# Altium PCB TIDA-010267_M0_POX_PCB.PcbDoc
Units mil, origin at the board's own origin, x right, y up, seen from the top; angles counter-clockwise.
Board outline 2000 x 1062.99 mil, 2 copper layers (Top Layer, Bottom Layer), stack 61.2 mil thick; 42 components, 32 nets, 124 pads, 44 vias.
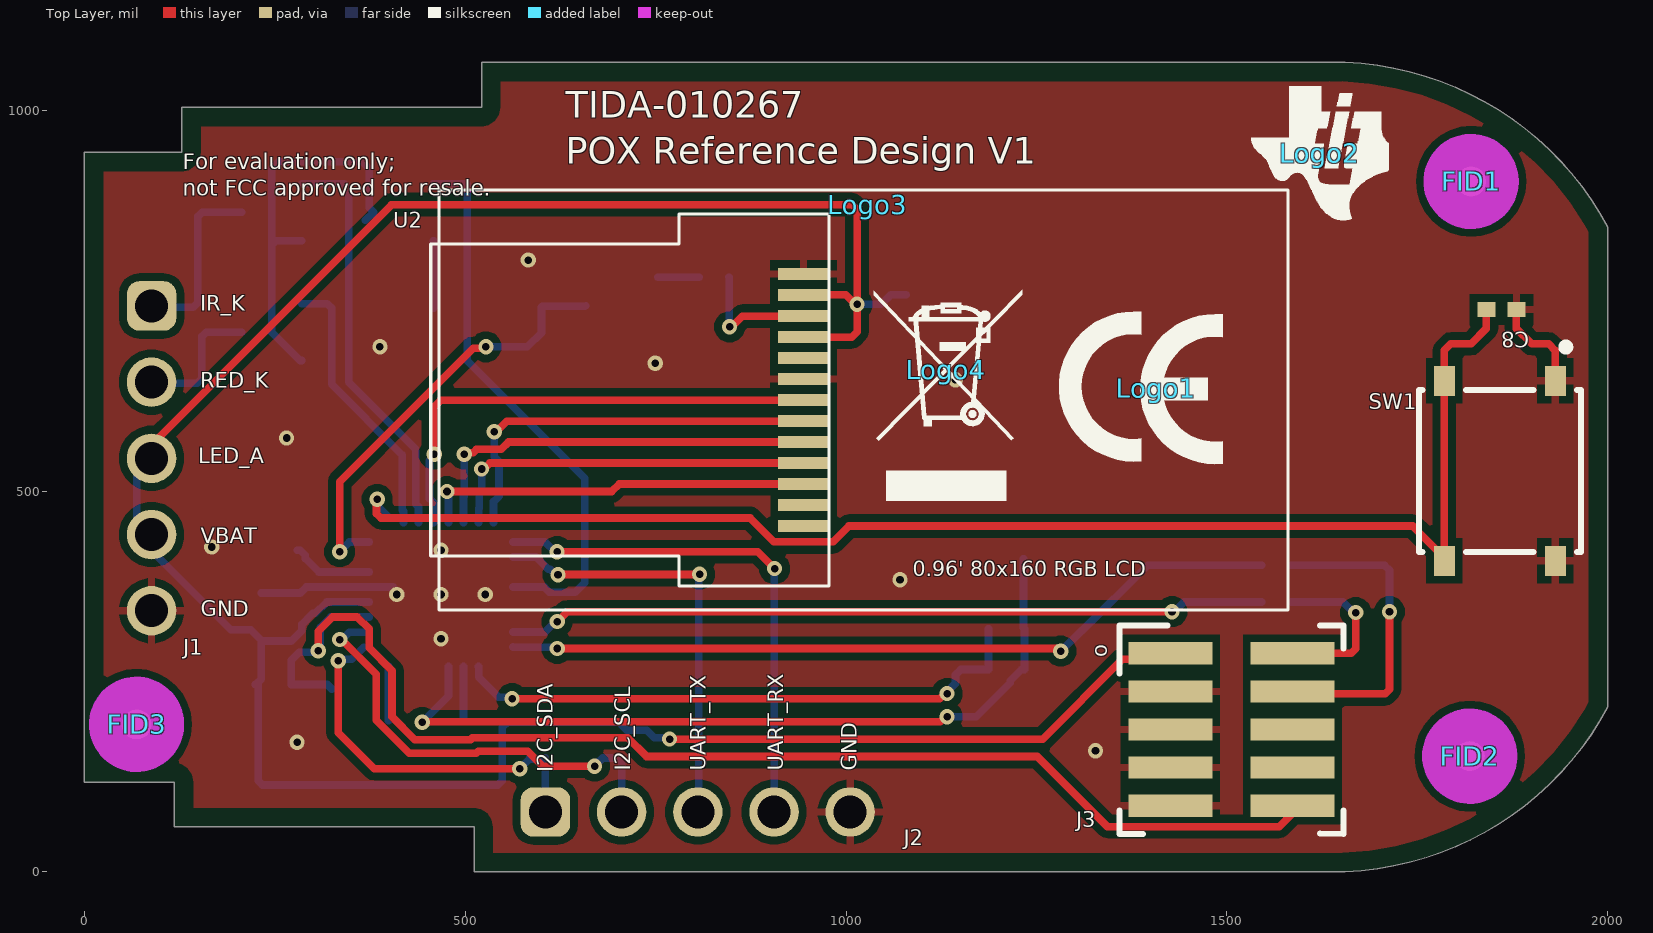
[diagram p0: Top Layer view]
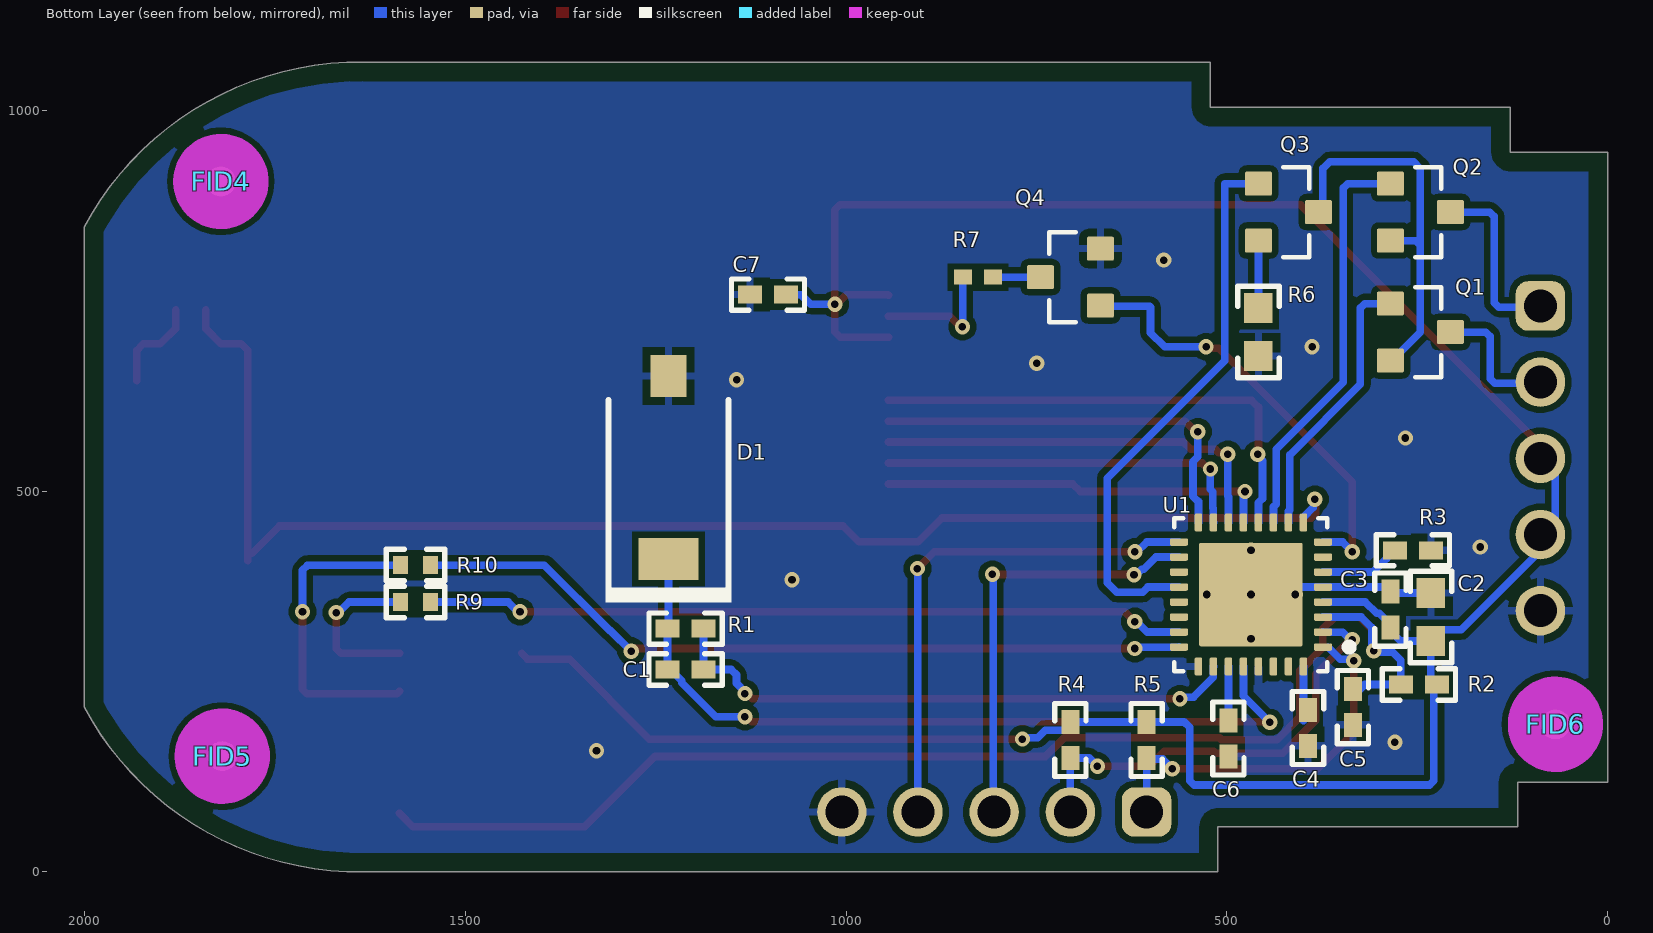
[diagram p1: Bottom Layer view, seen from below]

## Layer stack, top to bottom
Top Solder: solder mask 0.4, Solder Resist, Dk 3.5
Top Layer: signal copper 1.4
Dielectric1: dielectric 58.4, FR-4 High Tg, Dk 4.8
Bottom Layer: signal copper 1.4
Bottom Solder: solder mask 0.4, Solder Resist, Dk 3.5

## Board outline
0,118.11 0,944.88 127.95,944.88 127.95,1003.94 521.65,1003.94 521.65,1062.99 1633.86,1062.99 cw(c1638.25,652.6) 2000,846.46 2000,216.54 cw(c1638.25,410.39) 1633.86,0 511.81,0 511.81,59.06 118.11,59.06 118.11,118.11

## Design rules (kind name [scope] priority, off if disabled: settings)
AcuteAngle [All] p1: minimum=4.50000000000000E+0001 checktracksonly=FALSE
AssemblyTestPointUsage [All] p1: valid=2
BoardOutlineClearance BoardOutlineClearance_MountingHoles [OnCopper and InComponentClass('Mounting Holes')] p1: gap=39.37 ignorepadtopadclearanceinfootprint=FALSE
BoardOutlineClearance BoardOutlineClearance_Poly [OnCopper and IsPoly] p2: gap=25 ignorepadtopadclearanceinfootprint=FALSE
BoardOutlineClearance [OnCopper and Not InComponentClass('Logo') and not InComponentClass('FiducialMark') and not InRegion(1000,500,4000,800) and not StringText] p3: gap=10 ignorepadtopadclearanceinfootprint=FALSE
Clearance Clearance_1 [InNamedPolygon('GND_L01_P002')] p1: gap=10 ignorepadtopadclearanceinfootprint=FALSE except(0: Arc-Hole Track-Hole SMDPad-Hole THPad-Hole Via-Hole Fill-Hole Poly-Hole Region-Hole Text-Hole)
Clearance Clearance_Keepouts [((IsTrack Or IsArc) And Not InPoly) And IsFree and IsKeepOut vs ((IsTrack Or IsArc) And Not InPoly) And IsFree and IsKeepOut] p2: gap=0 ignorepadtopadclearanceinfootprint=FALSE
Clearance Clearance_Poly [InPolygon] p3: gap=8 ignorepadtopadclearanceinfootprint=TRUE
Clearance Clearance_FiducialMark [IsKeepOut and InComponentClass('FiducialMark') vs IsPad and InComponentClass('FiducialMark')] p4: gap=0 ignorepadtopadclearanceinfootprint=FALSE
Clearance [All] p5: gap=7.87 ignorepadtopadclearanceinfootprint=TRUE
ComponentClearance ComponentClearance_MountingHoles_FiducialMarks [InComponentClass('Mounting Holes') vs InComponentClass('FiducialMark')] p1: gap=50 collisioncheckmode=3 verticalgap=10 showdistances=FALSE
ComponentClearance ComponentClearance_Shunt [InComponentClass('Header') vs InComponentClass('Shunt')] p2: gap=0 collisioncheckmode=3 verticalgap=0 showdistances=FALSE
ComponentClearance ComponentClearance_Logo [InComponentClass('Logo')] p3: gap=0 collisioncheckmode=3 verticalgap=0 showdistances=FALSE
ComponentClearance ComponentClearance_ScrewToNut [(HasFootprint('NY PMS 440 0025 PH')) vs (HasFootprint('Keystone_1902C'))] p4: gap=5 collisioncheckmode=3 verticalgap=10 showdistances=FALSE
ComponentClearance ComponentClearance_MountingHoles [InComponentClass('Mounting Holes')] p5: gap=100 collisioncheckmode=3 verticalgap=100000 showdistances=FALSE
ComponentClearance ComponentClearance_SmallPassives [HasFootprint('0201*') or HasFootprint('0402*') or HasFootprint('0508') or HasFootprint('0603*') or HasFootprint('0612') or HasFootprint('0805*') or HasFootprint('0815*') or HasFootprint('0830*') or HasFootprint('1206*') or HasFootprint('1210*') or HasFootprint('1808*') or HasFootprint('1812*') or HasFootprint('1825*') or HasFootprint('2010*') or HasFootprint('2220*') or HasFootprint('2225*') or HasFootprint('2512*') or HasFootprint('2728*') or HasFootprint('3518*') vs HasFootprint('0201*') or HasFootprint('0402*') or HasFootprint('0508') or HasFootprint('0603*') or HasFootprint('0612') or HasFootprint('0805*') or HasFootprint('0815*') or HasFootprint('0830*') or HasFootprint('1206*') or HasFootprint('1210*') or HasFootprint('1808*') or HasFootprint('1812*') or HasFootprint('1825*') or HasFootprint('2010*') or HasFootprint('2220*') or HasFootprint('2225*') or HasFootprint('2512*') or HasFootprint('2728*') or HasFootprint('3518*')] p6: gap=14.96 collisioncheckmode=3 verticalgap=10 showdistances=FALSE
ComponentClearance ComponentClearance_THtoSMT [IsThruComponent vs IsSMTComponent] p7: gap=30 collisioncheckmode=3 verticalgap=30 showdistances=FALSE
ComponentClearance ComponentClearance_THtoTH [IsThruComponent vs IsThruComponent] p8: gap=20 collisioncheckmode=3 verticalgap=30 showdistances=FALSE
ComponentClearance [All] p9: gap=20 collisioncheckmode=3 verticalgap=10 showdistances=FALSE
DiffPairsRouting [All] p1: maxlimit=100 minlimit=10 mostfreqgap=10 toplayer_minwidth=15 toplayer_maxwidth=15 toplayer_prefwidth=15 bottomlayer_minwidth=15 bottomlayer_maxwidth=15 bottomlayer_prefwidth=15 maxuncoupledlength=1000
FabricationTestPointUsage TestPointUsage [All] p1: valid=2 allowmultiple=FALSE
FabricationTestpoint Testpoint [All] p1: side=3 testpointundercomponent=TRUE minsize=40 maxsize=100 preferedsize=60 minholesize=0 maxholesize=40 preferedholesize=32 testpointgrid=1 allowsidetop=TRUE allowsidebottom=TRUE usegrid=TRUE gridtolerance=0.01
FanoutControl Fanout_LCC [IsLCC] p1: bgadir=Out bgaviamode=Centered fanoutstyle=Auto fanoutdirection=Alternating viagrid=1 // Fanout_LCC (Default Rule)
FanoutControl Fanout_BGA [IsBGA] p2: bgadir=Out bgaviamode=Centered fanoutstyle=Auto fanoutdirection=Alternating viagrid=1 // Fanout_BGA (Default Rule)
HoleSize [All] p1: absolutevalues=TRUE maxlimit=251 minlimit=7.87 maxpercent=80.000 minpercent=20.000
MinimumAnnularRing MinimumAnnularRing_ThermalPadVias [IsVia and InAnyComponent] p1: minimumring=5.91
MinimumAnnularRing [All] p2: minimumring=7.87
MinimumSolderMaskSliver MinimumSolderMaskSliver_Logo [InComponentClass('Logo') vs InComponentClass('Logo')] p1: minsoldermaskwidth=0.7
MinimumSolderMaskSliver [All] p2: minsoldermaskwidth=3.94
PlaneConnect [All] p1: pad.planeconnectstyle=Relief pad.reliefexpansion=10 pad.reliefentries=4 pad.reliefconductorwidth=10 pad.reliefairgap=10 via.planeconnectstyle=Direct via.reliefexpansion=10 via.reliefentries=4 via.reliefconductorwidth=10 via.reliefairgap=10
PolygonConnect [All] p1: thpad.connectstyle=Relief thpad.reliefconductorwidth=10 thpad.reliefentries=4 thpad.polygonreliefangle="90 Angle" thpad.airgapwidth=10 smdpad.connectstyle=Relief smdpad.reliefconductorwidth=10 smdpad.reliefentries=4 smdpad.polygonreliefangle="90 Angle" smdpad.airgapwidth=10 via.connectstyle=Direct via.reliefconductorwidth=10 via.reliefentries=4 via.polygonreliefangle="90 Angle" via.airgapwidth=10
RoutingVias ThermalPadVias [IsVia and InAnyComponent] p1: holewidth=7.87 width=19.68 viastyle="Through Hole" minholewidth=7.87 minwidth=19.68 maxholewidth=12.99 maxwidth=23.62
RoutingVias [All] p2: holewidth=10 width=20 viastyle="Through Hole" minholewidth=7.87 minwidth=10 maxholewidth=40 maxwidth=65
SilkToSilkClearance SilkToSilkClearance_Pb-FreeLogo [(HasFootprint('Pb-Free_Overlay_Medium') OR HasFootprint('Pb-Free_Overlay_Small')) vs (HasFootprint('Pb-Free_Overlay_Medium') OR HasFootprint('Pb-Free_Overlay_Small'))] p1: silktosilkclearance=0
SilkToSilkClearance [All] p2: silktosilkclearance=3.94
SilkToSolderMaskClearance SilkToComponentPadClearance [(IsPad or IsFill or IsRegion) and InAnycomponent] p1: minsilkscreentomaskgap=5 clearancetoexposedcopper=TRUE
SilkToSolderMaskClearance "Silk to Solder Mask Opening" [All] p2: minsilkscreentomaskgap=3.94 clearancetoexposedcopper=FALSE
SolderMaskExpansion [All] p1: expansion=1.97 istentingtop=FALSE
UnRoutedNet [All] p1: checkbadconnections=TRUE
Width [All] p1: maxlimit=100 minlimit=6 preferedwidth=10 checkconnectedcopper=TRUE
17 further rules are at their usual default settings.

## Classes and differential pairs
component class FiducialMark: FID1 FID2 FID3 FID4 FID5 FID6
component class POX_M0_V1_Hardware: !PCB FID1 FID2 FID3 FID4 FID5 FID6 g Logo1 Logo2 Logo3 Logo4 ZZ1 ZZ2 ZZ3 ZZ4
component class POX_M0_V1_Schematic: C1 C2 C3 C4 C5 C6 C7 C8 D1 J1 J2 J3 Q1 Q2 Q3 Q4 R1 R2 R3 R4 R5 R6 R7 R9 R10 SW1 U1 U2
component class Header: J1 J2
component class Logo: g Logo1 Logo2 Logo3 Logo4
component class AssemblyNote: ZZ1 ZZ2 ZZ3 ZZ4

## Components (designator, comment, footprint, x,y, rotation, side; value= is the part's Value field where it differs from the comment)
C1 "C0402C100C8GACTU" 0402 1210.63,265.75 r180 bottom value=10pF
C2 "GRM188R61A106KAALD" 0603 232.28,334.65 r90 bottom value=10uF
C3 "GRM155R61A104KA01D" 0402 285.43,344.49 r90 bottom value=0.1uF
C4 "GRM155R61A474KE15D" 0402 393.59,188.98 r270 bottom value=0.47uF
C5 "GRM155R61A102KA01D" 0402 334.65,216.54 r270 bottom value=1000pF
C6 "GRM155R61E105KA12D" 0402 498.03,175.2 r270 bottom value=1uF
C7 "GRM155R61E105KA12D" 0402 1102.36,757.87 r180 bottom value=1uF
C8 "GRM155R61A104KA01D" 0402L 1860.24,738.19 r0 top value=0.1uF
D1 "BPW 34 SR" BPW34SR 1233,531 r270 bottom
FID1 "Fiducial" Fiducial10-30 1820.53,906.37 r0 top
FID2 "Fiducial" Fiducial10-30 1818.74,152.07 r90 top
FID3 "Fiducial" Fiducial10-30 68.9,193.8 r90 top
FID4 "Fiducial" Fiducial10-30 1820.53,906.37 r90 bottom
FID5 "Fiducial" Fiducial10-30 1818.74,152.07 r90 bottom
FID6 "Fiducial" Fiducial10-30 68.9,193.8 r90 bottom
J1 "61300511121" Wurth_61300511121 88.58,542.91 r270 top
J2 "61300511121" Wurth_61300511121 805.51,78.74 r0 top
J3 "FTSH-105-01-L-DV-K" Samtec_FTSH-105-01-x-DV-K 1505.91,187.01 r0 top
Logo1 "CE Mark" CE_Mark_5mm 1407.48,634.84 r0 top
Logo2 "Texas Instruments" TI_Symbol_Overlay_Small 1622.05,943.12 r0 top
Logo3 "FCC disclaimer" FCC_disclaimer 1028.35,875.98 r0 top
Logo4 "WEEE logo" WEEE_Minimum 1131.89,659.45 r0 top
Q1 "DMG3404L-7" FP-DMG3404L-7_SOT23-MFG 246.06,708.66 r180 bottom
Q2 "DMG3404L-7" FP-DMG3404L-7_SOT23-MFG 246.06,866.14 r180 bottom
Q3 "DMG3404L-7" FP-DMG3404L-7_SOT23-MFG 419.29,866.14 r180 bottom
Q4 "DMG3404L-7" FP-DMG3404L-7_SOT23-MFG 705.51,780.71 r0 bottom
R1 "CRCW04022M00FKED" 0402 1210.63,319.37 r0 bottom value=2.00Meg
R2 "RC0402FR-0747KL" 0402 248.03,246.06 r180 bottom value=47.0k
R3 "RG1005P-104-B-T5" 0402 255.91,422.24 r180 bottom value=100k
R4 "ERJ-2RKF1002X" 0402 705.51,173.23 r90 bottom value=10.0k
R5 "ERJ-2RKF1002X" 0402 605.51,173.23 r90 bottom value=10.0k
R6 "RC0603FR-0710RL" 0603 458.66,708.66 r90 bottom value=10.0
R7 "CRCW040210R0JNED" 0402L 826.77,780.71 r0 bottom value=10
R9 "CPF0402B27RE1" CPF0402 1564.96,354.33 r180 bottom value=27
R10 "CPF0402B27RE1" CPF0402 1564.96,402.76 r180 bottom value=27
SW1 "PTS526SK15SMTR2LFS" FP-PTS526SK15SMTR2LFS-MFG 1858.13,526.57 r270 top
U1 "MSPM0L1306SRHB" RHB0032N-MFG 468.5,364.17 r0 bottom
U2 "0.96 inch LCD RGB display" MDT0096A2IS-SPI 1580,895 r180 top
ZZ1 "This Assembly Note is for PCB labels only" AssemblyNoteLabel 0,2400 r0 top
ZZ2 "These assemblies are ESD sensitive, ESD precautions shall be observed." AssemblyNote 0,2300 r0 top
ZZ3 "These assemblies must be clean and free from flux and all contaminants. Use of no clean flux is not acceptable." AssemblyNote 0,2200 r0 top
ZZ4 "These assemblies must comply with workmanship standards IPC-A-610 Class 2, unless otherwise specified." AssemblyNote 0,2100 r0 top

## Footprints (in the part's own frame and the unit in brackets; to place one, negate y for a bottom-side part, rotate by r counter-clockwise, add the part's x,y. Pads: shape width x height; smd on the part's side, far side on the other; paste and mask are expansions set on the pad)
0402 [mm] "0402 from SM-752 data"
  rect 0.8x0.6 smd: 1(-0.6,0) 2(0.6,0)
  silkscreen extent -1.22,-0.52 1.22,0.52, body extent -0.55,-0.3 0.55,0.3, height 0.6
0402L [mm] "0402 from SM-752 data"
  rect 0.6x0.5 smd: 1(-0.5,0) 2(0.5,0)
  body extent -0.55,-0.3 0.55,0.3, height 0.6
0603 [mm] "0603 from SM-752 data"
  rect 1x0.95 smd: 1(-0.8,0) 2(0.8,0)
  silkscreen extent -1.52,-0.69 1.52,0.69, body extent -0.87,-0.47 0.87,0.47, height 1
AssemblyNote [mil] "Assembly Note"
AssemblyNoteLabel [mil] "Assembly Note for PCB Labels"
BPW34SR [mm] "SMD, 2-Leads, Body 3.85x4.4mm"
  rect 1.4x1.2 smd paste-0.05 mask+0.05: 1(-3.05,0)
  rect 1.4x2 smd paste-0.05 mask+0.05: 2(3.05,0)
  silkscreen extent -2.25,-2.1 4.5,2.1, body extent -2.25,-2 2.25,2, height 1.2
CE_Mark_5mm [mil] "Minimum text height for CE Mark"
  silkscreen extent -128,-99 87,101
CPF0402 [mm] "TE Connectivity"
  rect 0.5x0.6 smd: 1(-0.5,0) 2(0.5,0)
  silkscreen extent -0.97,-0.52 0.98,0.53, body extent -0.55,-0.27 0.55,0.27, height 0.35
FCC_disclaimer [mil]
Fiducial10-30 [mm]
  round 1 smd mask+1: 1(0,0)
  Top Layer keep-out circle w1.678: c0,0 r0.75
FP-DMG3404L-7_SOT23-MFG [mm]
  rrect13% 0.9x0.8 smd paste+0 mask+0: 1(-1,0.95) 2(-1,-0.95) 3(1,0)
  silkscreen extent -0.18,-1.5 0.7,1.5, body extent -1.2,-1.45 1.2,1.45, height 1.1
FP-PTS526SK15SMTR2LFS-MFG [mm]
  rect 1x0.7 smd paste+0 mask+0: 1(-3,1.85) 2(3,1.85) 3(-3,-1.85) 4(3,-1.85)
  silkscreen extent -4.25,-2.7 2.7,2.7, body extent -3.6,-2.8 3.6,2.8, height 0.25
MDT0096A2IS-SPI [mm]
  rect 1.7x0.4 smd: 1(16.15,11.2) 2(16.15,10.5) 3(16.15,9.8) 4(16.15,9.1) 5(16.15,8.4) 6(16.15,7.7) 7(16.15,7) 8(16.15,6.3) 9(16.15,5.6) 10(16.15,4.9) 11(16.15,4.2) 12(16.15,3.5) 13(16.15,2.8)
  silkscreen extent 0,0 28.57,14
RHB0032N-MFG [mm]
  rrect40% 0.6x0.25 smd paste+0 mask+0: 1(-2.4,1.75) 2(-2.4,1.25) 3(-2.4,0.75) 4(-2.4,0.25) 5(-2.4,-0.25) 6(-2.4,-0.75) 7(-2.4,-1.25) 8(-2.4,-1.75) 17(2.4,-1.75) 18(2.4,-1.25) 19(2.4,-0.75) 20(2.4,-0.25) 21(2.4,0.25) 22(2.4,0.75) 23(2.4,1.25) 24(2.4,1.75)
  rrect40% 0.25x0.6 smd paste+0 mask+0: 9(-1.75,-2.4) 10(-1.25,-2.4) 11(-0.75,-2.4) 12(-0.25,-2.4) 13(0.25,-2.4) 14(0.75,-2.4) 15(1.25,-2.4) 16(1.75,-2.4) 25(1.75,2.4) 26(1.25,2.4) 27(0.75,2.4) 28(0.25,2.4) 29(-0.25,2.4) 30(-0.75,2.4) 31(-1.25,2.4) 32(-1.75,2.4)
  rrect3% 3.45x3.45 smd paste-1000 mask+0: 33(0,0)
  silkscreen extent -3.4,-2.55 2.55,2.55, body extent -2.5,-2.5 2.5,2.5, height 0.9
Samtec_FTSH-105-01-x-DV-K [mm] "Header(Shrouded), 1.27mm, 5x2, SMT"
  rect 2.79x0.74 smd: 1(-2.035,2.54) 2(2.035,2.54) 3(-2.035,1.27) 4(2.035,1.27) 5(-2.035,0) 6(2.035,0) 7(-2.035,-1.27) 8(2.035,-1.27) 9(-2.035,-2.54) 10(2.035,-2.54)
  silkscreen extent -3.73,-3.48 3.73,3.48, body extent -2.92,-3.18 2.92,3.17, height 6.13
TI_Symbol_Overlay_Small [mil]
  silkscreen extent -90,-88 91,88
WEEE_Minimum [mil] "WEEElie bin"
  silkscreen extent -95,-172 99,104
Wurth_61300511121 [mm] "Header, 2.54mm, 5x1, TH"
  rrect50% 1.65x1.65 hole 1.1: 1(-5.08,0)
  round 1.65 hole 1.1: 2(-2.54,0) 3(0,0) 4(2.54,0) 5(5.08,0)
  body extent -6.35,-1.27 6.35,1.27, height 8.54

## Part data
C1: library part CMP-0064914-2, "CAP, CERM, 10 pF, 10 V,+/- 2.5%, C0G/NP0, 0402", Cap_Case=0402, Manufacturer=Kemet, Supplier Part Number 1=399-8939-1-ND, TempCo=C0G/NP0, Tolerance_%=2.5%, Value1=Unknown, Value2=10V, ValueDisplayed=10pF
C2: library part CMP-0086193-1, "CAP, CERM, 10 µF, 10 V,+/- 10%, X5R, 0603", Cap_Case=0603, Manufacturer=MuRata, TempCo=X5R, Tolerance_%=10%, Value2=10V, ValueDisplayed=10µF
C3: library part CMP-0006562-2, "CAP, CERM, 0.1 uF, 10 V, +/- 10%, X5R, 0402", Cap_Case=0402, Manufacturer=MuRata, Supplier Part Number 1=490-1318-1-ND, TempCo=X5R, Tolerance_%=10%, Value1=Unknown, Value2=10V, ValueDisplayed=100nF
C4: library part CMP-0006580-2, "CAP, CERM, 0.47 uF, 10 V, +/- 10%, X5R, 0402", Cap_Case=0402, Manufacturer=MuRata, Supplier Part Number 1=490-3264-1-ND, TempCo=X5R, Tolerance_%=10%, Value1=Unknown, Value2=10V, ValueDisplayed=0.47uF
C5: library part CMP-0006560-2, "CAP, CERM, 1000 pF, 10 V, +/- 10%, X5R, 0402", Cap_Case=0402, Manufacturer=MuRata, Supplier Part Number 1=GRM155R61A102KA01D-ND, TempCo=X5R, Tolerance_%=10%, Value1=Unknown, Value2=10V, ValueDisplayed=1000pF
C6 C7: library part CMP-0006608-2, "CAP, CERM, 1 uF, 25 V, +/- 10%, X5R, 0402", Cap_Case=0402, Manufacturer=MuRata, Supplier Part Number 1=490-10017-1-ND, TempCo=X5R, Tolerance_%=10%, Value1=Unknown, Value2=25V, ValueDisplayed=1uF
C8: library part CMP-0006562-2, "CAP, CERM, 0.1 uF, 10 V, +/- 10%, X5R, 0402", Cap_Case=0402, Manufacturer=MuRata, Supplier Part Number 1=490-1318-1-ND, TempCo=X5R, Tolerance_%=10%, Value1=Unknown, Value2=10V, ValueDisplayed=0.1uF
D1: library part CMP-0005335-2, "PIN Photodiode, SMD", Manufacturer=OSRAM, Supplier Part Number 1=751-1501-1-ND
FID1 FID2 FID3 FID4 FID5 FID6: library part CMP-0077181-1, "Fiducial mark.  There is nothing to buy or mount.", Manufacturer=N/A
J1 J2: library part CMP-0084909-1, "Header, 2.54mm, 5x1, Gold, TH", Color=Black, Current_A=3A, Manufacturer="Wurth Elektronik", Voltage_V=250V
J3: library part CMP-0075634-2, "Header(Shrouded), 1.27mm, 5x2, Gold, SMT", Color=Black, Current_A=3.3A, Manufacturer=Samtec, Supplier Part Number 1=SAM8799-ND
Logo1: library part CMP-0074844-1
Logo2: library part CMP-0074838-1, "Texas Instrument Corporate Signature"
Logo3: library part CMP-0074847-1, "FCC_disclaimer"
Logo4: library part CMP-0074769-1
Q1 Q2 Q3 Q4: library part CMP-0001689-1, "MOSFET N-Channel 30 V 4.2A (Ta) 780mW (Ta) Surface Mount SOT-23-3", Digikey Part Number=DMG3404L-7DICT-ND, Drain to Source Breakdown Voltage=30V, Input Capacitace At Vds="641pF @ 15V", Manufacturer="Diodes Inc.", Mouser Part Number=621-DMG3404L-7, Operating Temperature Range="-55°C to +150°C", Power_W=0.78W, Pulse Drain Current=30A, Typ Forward Diode Voltage=0.75V
R1: library part CMP-0026245-2, "RES, 2.00 M, 1%, 0.063 W, AEC-Q200 Grade 0, 0402", Manufacturer=Vishay-Dale, Power_W=63mW, Supplier Part Number 1=541-2.00MLCT-ND, TempCo="100 ppm/C", Tolerance_%=1%, Value2=0.063W, Value_Code=2M00, ValueDisplayed=2.00M
R2: library part CMP-0026737-1, "RES, 47.0 k, 1%, 0.0625 W, 0402", Manufacturer="Yageo America", Power_W=62.5mW, Supplier Part Number 1=311-47.0KLRCT-ND, TempCo="100 ppm/C", Tolerance_%=1%, Value2=0.0625W, Value_Code=47k0, ValueDisplayed=47.0k
R3: library part CMP-0026815-1, "RES, 100 k, 0.1%, 0.063 W, 0402", Manufacturer="Susumu Co Ltd", Power_W=63mW, Supplier Part Number 1=RG10P100KBCT-ND, TempCo="25 ppm/C", Tolerance_%=0.1%, Value2=0.063W, Value_Code=100k
R4 R5: library part CMP-0026658-1, "RES, 10.0 k, 1%, 0.1 W, 0402", Manufacturer=Panasonic, Power_W=100mW, Supplier Part Number 1=P10.0KLCT-ND, TempCo="100 ppm/C", Tolerance_%=1%, Value2=0.1W, Value_Code=10k0, ValueDisplayed=10.0k
R6: library part CMP-0022751-4, "RES, 10.0, 1%, 0.1 W, 0603", Manufacturer=Yageo, Power_W=100mW, Supplier Part Number 1=311-10.0HRCT-ND, TempCo="100 ppm/C", Tolerance_%=1%, Value2=0.1W, Value_Code=10R0, ValueDisplayed=10.0
R7: library part CMP-0026827-3, "RES, 10, 5%, 0.063 W, AEC-Q200 Grade 0, 0402", Manufacturer=Vishay-Dale, Power_W=63mW, Supplier Part Number 1=541-10JCT-ND, TempCo="200 ppm/C", Tolerance_%=5%, Value2=0.063W, Value_Code=10R0, ValueDisplayed=10
R9 R10: library part CMP-0026767-1, "RES, 27, 0.1%, 0.063 W, 0402", Manufacturer="TE Connectivity", Power_W=63mW, Supplier Part Number 1=A102751CT-ND, TempCo="25 ppm/C", Tolerance_%=0.1%, Value2=0.063W, Value_Code=27R0, ValueDisplayed=27.0
SW1: library part CMP-10040-000013-1, "TACT 5.2 X 5.2, 1.5 MM H, 260GF,", Contact Current Rating=50mA, Contact Resistance=100mΩ, Manufacturer=C&K, Operating Force=250gf, Temperature="-20°C to +70°C", Temperature Range High=+70°C, Temperature Range Low=-20°C, Voltage Rating Dc=12V
U1: library part CMP-0093968-1, "MSPM0L130x Mixed-Signal Microcontrollers", Frequency_Fixed=32MHz, Manufacturer="Texas Instruments", Max Supply Voltage=3.6V, Min Supply Voltage=1.62V, Operating Temperature Range="-40°C to +125°C"
U2: library part GMT096-01
ZZ1: library part CMP-0003616-3
ZZ2: library part CMP-0077236-1
ZZ3: library part CMP-0077237-1
ZZ4: library part CMP-0077238-1

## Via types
v1: diameter 20, hole 10, Top Layer to Bottom Layer, tented both sides, 39 vias
v2: diameter 20, hole 10, Top Layer to Bottom Layer, tented top, 5 vias

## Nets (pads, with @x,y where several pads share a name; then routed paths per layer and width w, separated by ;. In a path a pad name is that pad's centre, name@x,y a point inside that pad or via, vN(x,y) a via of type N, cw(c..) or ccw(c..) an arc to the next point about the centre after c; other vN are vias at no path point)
CURRENT_CTRL: Q3.1 U1.20 | length 734.3
  Bottom Layer w10: Q3.1 502.92,903.54 502.92,671.26 657.28,516.9 657.28,379.87 644.56,367.15 610.61,367.15 603.75,374.02 U1.20
GND: C2.2 C3.2 C4.2 C5.2 C6.2 C7.1 C8.2 D1.1 J1.5 J2.5 J3.3 J3.5 J3.7 J3.9 Q4.2 R3.2 R6.1 SW1.1 SW1.2 U1.5 U1.25 U1.29 U1.33 U2.8 U2.13 | length 316
  Top Layer w10: C8.2 1879.92,713.35 1899.94,693.32 1922.05,693.32 1930.96,684.42 SW1.1
  Bottom Layer w10: C2.2 283.47,366.14 C3.2 291.34,374.02 U1.5 405.59,374.02 410.43,369.17 v2(410.43,364.17)
  other v1: 1327.42,159.1 279.53,170.36 1070.86,383.69 167.49,426.52 265.75,569.57 1143.59,646.08 749.78,667.77 388.22,689.35 583,803.15
  other v2: 468.5,306.1 468.5,364.17 526.58,364.17 468.5,422.24
I2C_SCL: J2.2 R4.1 U1.2 | length 594.5
  Top Layer w10: v1(335.43,305.04) 337.91,305.04 383.38,259.57 383.38,199.19 426.82,155.75 514.58,155.75 517.23,158.4 582.52,158.4 602.08,138.84 v1(670.08,138.84)
  Bottom Layer w10: v1(335.43,305.04) 338.14,305.04 347.98,314.88 373.94,314.88 U1.2 ; v1(670.08,138.84) 680.84,149.61 R4.1 J2.2
I2C_SDA: J2.1 R5.1 U1.1 | length 503.9
  Top Layer w10: v1(333.43,277.17) 333.43,182.9 380.8,135.53 v1(571.65,135.53)
  Bottom Layer w10: v1(333.43,277.17) 335.34,279.08 351.09,279.08 U1.1@367.2,295.2 ; v1(571.65,135.53) 584.38,148.26 604.16,148.26 R5.1 J2.1
IR_LED: J1.1 Q2.3 | length 255.7
  Bottom Layer w10: J1.1@68.9,741.34 143.26,741.34 149.11,747.2 149.11,860.28 154.97,866.14 Q2.3
IR_LED_Q: Q2.1 U1.11 | length 541.2
  Bottom Layer w10: Q2.1 341.35,903.54 347.2,897.69 347.2,642.96 435.52,554.65 435.52,482.57 438.9,479.2 438.9,458.74 U1.11
LCD_BLK: Q4.1 U1.8 | length 573.9
  Top Layer w10: v1(335.43,420.34) 335.43,512.28 510.59,687.44 525.45,687.44 v1(527.36,689.35)
  Bottom Layer w10: v1(335.43,420.34) 348.16,433.07 U1.8 ; v1(527.36,689.35) 581.86,689.35 600.39,707.88 600.39,741.34 601.38,742.32 657.28,742.32 Q4.1@658.27,743.31
LEDK: R7.2 U2.11 | length 168.2
  Top Layer w10: v1(847.24,715.61) 849.95,715.61 863.98,729.65 U2.11
  Bottom Layer w10: R7.2 846.85,780.32 846.85,716.01 v1(847.24,715.61)
NetC6_1: C6.1 U1.27 | length 70.9
  Bottom Layer w10: C6.1 U1.27
NetJ3_2: J3.2 R9.1 | length 223
  Top Layer w10: J3.2 1663.08,287.01 1668.93,292.87 v1(1668.93,340.49)
  Bottom Layer w10: R9.1 1652.39,354.33 1666.23,340.49 v1(1668.93,340.49)
NetJ3_4: J3.4 R10.1 | length 419
  Top Layer w10: J3.4 1589.22,233.81 1707.53,233.81 1713.38,239.67 v1(1713.38,341.6)
  Bottom Layer w10: R10.1 1706.74,402.76 1713.38,396.11 v1(1713.38,341.6)
NetQ1_2: Q1.2 Q2.2 Q3.3 | length 521.4
  Bottom Layer w10: Q1.2 283.46,671.26 246.06,708.66 246.06,822.88 ; Q2.2 251.92,828.74 246.06,822.88 ; Q3.3@369.17,855.39 Q3.3 374.02,872.05 374.02,923.28 365.13,932.17 254.95,932.17 246.06,923.28 246.06,822.88
NetQ3_2: Q3.2 R6.2 | length 88.6
  Bottom Layer w10: R6.2 Q3.2
NetQ4_3: Q4.3 R7.1 | length 54.3
  Bottom Layer w10: Q4.3@752.76,780.71 R7.1
NRST: C5.1 J3.10 R2.1 U1.3 | length 1714.4
  Top Layer w10: v1(307.2,290.27) 307.2,315.84 326,334.65 358.73,334.65 374.02,319.37 374.02,294.21 404.12,264.1 404.12,203.73 434.22,173.62 507.18,173.62 509.83,176.27 713.49,176.27 738.19,151.57 1251.23,151.57 1343.24,59.57 1568.43,59.57 J3.10@1586.02,77.17
  Bottom Layer w10: v1@305.12,293.37 307.59,293.37 309.11,294.89 309.11,298.61 310.12,299.62 310.12,320.87 323.9,334.65 U1.3 ; v1(307.2,290.27) 305.34,288.41 282.2,288.41 271.65,277.87 R2.1 318.9,246.06 C5.1@324.8,240.16
OPA_FB: C1.2 R1.1 U1.26 | length 772.5
  Top Layer w10: v1(561.75,227.42) 1123.28,227.42 1129.97,234.12 v1(1132.68,234.12)
  Bottom Layer w10: U1.26 517.8,269.61 517.8,255.5 543.96,229.34 559.84,229.34 v1(561.75,227.42) ; v1(1132.68,234.12) 1132.68,236.82 1143.72,247.86 1143.72,258.68 1150.79,265.75 C1.2 R1.1
OPA_IN-: C1.1 D1.2 R1.2 U1.28 | length 1053.9
  Top Layer w10: v1(443.7,196.5) 444.52,197.32 1123.49,197.32 1129.97,203.8 v1(1132.68,203.8)
  Bottom Layer w10: v1(443.7,196.5) 478.35,231.15 U1.28 ; v1(1132.68,203.8) 1170.83,203.8 1215.63,248.6 1215.63,251.06 1230.31,265.75 C1.1 R1.2 1233,320.62 D1.2
RED_LED: J1.2 Q1.3 | length 198.3
  Bottom Layer w10: J1.2@68.9,641.34 148.38,641.34 154.23,647.2 154.23,702.8 160.09,708.66 Q1.3
RED_LED_Q: Q1.1 U1.10 | length 362.5
  Bottom Layer w10: Q1.1 318.94,746.06 324.8,740.2 324.8,640.09 417.65,547.24 417.65,475.17 419.21,473.6 419.21,458.74 U1.10
RESET: U1.16 U2.6 | length 536.6
  Top Layer w10: v1(538.19,577.82) 540.89,577.82 554.93,591.85 U2.6
  Bottom Layer w10: U1.16 537.4,486.25 544.61,493.45 544.61,538.41 538.19,544.82 v1(538.19,577.82)
ROSC: R3.1 U1.6 | length 108.6
  Bottom Layer w10: R3.1 283.46,422.24 290.28,415.43 290.28,411.5 307.99,393.78 373.94,393.78 U1.6
SPI_CS: U1.12 U2.7 | length 645.9
  Top Layer w10: v1(459.45,548.29) 458.66,549.08 458.66,610.24 467.84,619.41 U2.7
  Bottom Layer w10: U1.12 458.66,484.71 453.39,489.98 453.39,539.53 459.45,545.58 v1(459.45,548.29)
SPI_D/C: U1.14 U2.5 | length 542.2
  Top Layer w10: v1(498.82,548.29) 500.73,550.2 510.66,550.2 515.06,554.61 547.32,554.61 557.01,564.29 U2.5
  Bottom Layer w10: U1.14 498.03,492.41 499.14,493.52 499.14,518.29 498.82,518.62 v1(498.82,548.29)
SPI_SCL: U1.15 U2.4 | length 497.6
  Top Layer w10: v1(521.73,528.93) 524.44,528.93 532.24,536.73 U2.4
  Bottom Layer w10: U1.15 517.8,458.74 517.8,477.04 518.52,477.76 518.52,498.93 521.73,502.14 v1(521.73,528.93)
SPI_SDA: U1.13 U2.3 | length 513.6
  Top Layer w10: v1(476.27,499.45) 692.48,499.45 702.2,509.17 U2.3
  Bottom Layer w10: v1(476.27,499.45) 476.27,496.75 478.35,494.67 U1.13
SWCLK: R10.2 U1.24 | length 1031.3
  Top Layer w10: v1(620.86,293.37) 1275.71,293.37 1279.29,289.79 v1(1282,289.79)
  Bottom Layer w10: U1.24 563.07,295.2 619.04,295.2 v1(620.86,293.37) ; v1(1282,289.79) 1309.19,316.98 1310.09,316.98 1395.87,402.76 R10.2
SWDIO: R9.2 U1.23 | length 998.6
  Top Layer w10: v1(620.86,328.61) 633.86,341.6 v1(1427.95,341.6)
  Bottom Layer w10: U1.23 604.51,314.96 618.16,328.61 v1(620.86,328.61) ; v1(1427.95,341.6) 1430.66,341.6 1443.39,354.33 R9.2
UART_RX: J2.4 U1.17 | length 677.5
  Top Layer w10: v1(620.84,420.34) 884.15,420.34 v1(906.3,398.19)
  Bottom Layer w10: U1.17 605.4,433.07 618.13,420.34 v1(620.84,420.34) ; J2.4 905.9,79.13 905.9,397.8 v1(906.3,398.19)
UART_TX: J2.3 U1.18 | length 567.9
  Top Layer w10: v1(621.99,390.02) 622.38,390.42 807.48,390.42 v1(807.87,390.81)
  Bottom Layer w10: U1.18 593.2,413.39 609.12,397.46 611.84,397.46 619.28,390.02 v1(621.99,390.02) ; J2.3 806.69,79.92 806.69,389.63 v1(807.87,390.81)
VBAT: C2.1 C3.1 C7.2 J1.3 J1.4 J3.1 R2.2 R4.2 R5.2 U1.4 U2.10 U2.12 | length 3474.7
  Top Layer w10: J1.3@68.9,541.34 403.54,875.98 1007.92,875.98 1014.57,869.34 v1(1014.57,745.14) ; v1(768.5,174.45) 1258.12,174.45 1362.88,279.21 1417.99,279.21 J3.1 ; U2.10 1007.59,702.09 1014.57,709.06 v1(1014.57,745.14) ; U2.12 944.51,757.54 999.46,757.54 1011.86,745.14 v1(1014.57,745.14)
  Bottom Layer w10: J1.3@68.9,541.34 68.9,441.34 192.4,317.84 218.58,317.84 232.28,304.13 C2.1 ; R2.2 225.47,246.06 232.28,252.87 C2.1 ; R2.2@228.35,246.06 228.35,119.98 234.2,114.13 542.92,114.13 548.78,119.98 548.78,189.78 555.85,196.85 R5.2 R4.2 705.51,192.92 712.32,186.1 738.5,186.1 748.24,176.36 766.59,176.36 v1(768.5,174.45) ; U1.4 318.31,354.33 303.46,339.49 300.12,339.49 285.43,324.8 C3.1 285.43,316.93 271.66,303.15 C2.1 ; v1(1014.57,745.14) 1046.32,745.14 1059.06,757.87 C7.2
VCORE: C4.1 U1.32 | length 70.9
  Bottom Layer w10: C4.1@399.61,198.82 U1.32
WAKE_BTN: C8.1 SW1.3 SW1.4 U1.9 | length 1839.7
  Top Layer w10: v1(384.64,489.24) 383.86,488.45 383.86,470.42 389.72,464.57 874.11,464.57 905.38,433.31 982.97,433.31 1003.72,454.05 1743.83,454.05 SW1.4@1779.26,418.62 ; SW1.4 1785.29,684.67 1793.94,693.32 1820.53,693.32 1840.55,713.35 C8.1
  Bottom Layer w10: 386.56,478.45 U1.9@399.53,465.47
pads on no net: FID1.1 FID2.1 FID3.1 FID4.1 FID5.1 FID6.1 J3.6 J3.8 U1.7 U1.19 U1.21 U1.22 U1.30 U1.31 U2.1 U2.2 U2.9

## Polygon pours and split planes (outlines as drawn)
GND on Top Layer "GND_L01_P002" (solid, pour order 2): 9.84,935.04 9.84,127.95 127.95,127.95 127.95,68.9 520.53,68.9 520.53,9.84 1683.07,9.84 1779.26,45 1871.06,87.6 1988.19,216.54 1988.19,901.07 1763.69,1053.15 537.4,1053.15 537.4,994.09 137.8,994.09 137.8,935.04
GND on Bottom Layer "GND_L02_P000" (solid, pour order 0): 9.84,935.04 9.84,127.95 127.95,127.95 127.95,68.9 526.58,68.9 526.58,9.84 1663.39,9.84 1761.81,29.53 1879.92,88.58 1899.61,108.27 1988.19,216.54 1988.19,846.46 1879.92,984.32 1673.23,1053.15 533.14,1053.15 533.14,994.09 137.8,994.09 137.8,935.04

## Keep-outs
Keep-Out Layer:
  text ".Layer_Name" at 572.5,-1004.99 h60

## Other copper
Top Layer:
  text ".Layer_Name" at 493.76,-1004.99 h60
Bottom Layer:
  text ".Layer_Name" at 572.5,-1004.99 h60

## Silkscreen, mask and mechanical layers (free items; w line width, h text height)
Top Overlay:
  text "TIDA-010267 / POX Reference Design V1" at 632.06,917.86 h60
  text "IR_K" at 152.33,736.43 h20
  text "RED_K" at 152.38,635.42 h20
  text "LED_A" at 149.98,536.26 h20
  text "VBAT" at 153.11,431.29 h20
  text "GND" at 153.11,335.69 h20
  text "o" at 1342.62,281.99 h20 r90
  text "I2C_SCL" at 716.59,132.74 h20 r90
  text "UART_TX" at 815.8,132.74 h20 r90
  text "UART_RX" at 917.48,132.74 h20 r90
  text "GND" at 1014.15,132.74 h20 r90
  text "I2C_SDA" at 615.41,130.77 h20 r90
  text ".Layer_Name" at 572.5,-1004.99 h60
Bottom Overlay:
  text ".Layer_Name" at 572.5,-1004.99 h60
Top Paste:
  text ".Layer_Name" at 572.5,-1004.99 h60
Bottom Paste:
  text ".Layer_Name" at 572.5,-1004.99 h60
Top Solder:
  text ".Layer_Name" at 572.5,-1004.99 h60
  text ".Layer_Name" at 572.5,-1004.99 h60
Bottom Solder:
  text ".Layer_Name" at 572.5,-1004.99 h60
Drill Guide:
  text ".Layer_Name" at 572.5,-1004.99 h60
M1 Board Outline:
  the board outline again, w10
  text ".Layer_Name" at 493.76,-1004.99 h60
M2 Board Dimensions:
  rectangle: 120.5,-546.5 495.5,-421.5
  rectangle: -4.5,-421.5 120.5,-296.5
  lines w7: -4.5,-421.5 995.5,-421.5 ; 120.5,-546.5 120.5,-296.5 ; 245.5,-546.5 245.5,-296.5 ; 495.5,-546.5 495.5,-296.5 ; 745.5,-546.5 745.5,-296.5 ; -4.5,-546.5 -4.5,-296.5 995.5,-296.5 995.5,-546.5 -4.5,-546.5
  text ".Layer_Name" at 493.76,-1004.99 h60
M3 3D STEP Top:
  text ".Layer_Name" at 493.76,-1004.99 h60
M4 3D STEP Bottom:
  text ".Layer_Name" at 493.76,-1004.99 h60
M5 Assembly Top:
  lines w10: -316.18,-1076.67 5533.85,-1076.67 ; -316.18,-873.33 5533.85,-873.33 ; -316.18,-670 -316.18,-1280 3688.82,-1280 ; 1259.82,-1280 -315.68,-1280 -315.68,-670 5533.85,-670 5533.85,-1280 3212.44,-1280 ; 1967.71,-1280 1967.71,-670 ; 2998.49,-873.33 2998.49,-670 ; 3720.38,-873.33 3720.38,-670 ; 4224.27,-1286.5 4224.27,-1083.67
  text "COMPONENTS MARKED 'DNP' SHOULD NOT BE POPULATED." at 1026.95,-465 h60
  text "ASSEMBLY VARIANT:" at 1026.45,-580.5 h60
  text ".VariantName" at 2054.58,-580.5 h60
  text "PCB VIEWED FROM TOP SIDE" at -272.37,-802.17 h60
  text "BOARD #:" at 2011.22,-802.17 h60
  text ".PRJ_Number" at 2470.1,-802.17 h60
  text "REV:" at 3157.12,-802.17 h60
  text ".PCB_Rev" at 3389.57,-802.17 h60
  text "SVN REV:" at 3790.4,-802.17 h60
  text ".VersionControl_RevNumber" at 4284.59,-802.17 h60
  text "TID #:" at 2011.22,-1005.5 h60
  text ".TID" at 2470.1,-1005.5 h60
  text "PLOT NAME =" at -272.37,-1210.84 h60
  text ".plot_File_Name" at 493.76,-1210.84 h60
  text "GENERATED    :" at 2013.22,-1210.84 h60
  text ".Print_Date" at 2737.05,-1210.84 h60
  text ".Print_Time" at 3328.25,-1210.84 h60
  text "TEXAS INSTRUMENTS" at 4395.9,-1210.84 h60
M6 Assembly Bottom:
  lines w10: -316.68,-873.83 5533.85,-873.83 ; -314.68,-1077.17 5533.85,-1077.17 ; 1008.64,-1287 1008.64,-1084.17 ; 1551.9,-873.83 1551.9,-670.5 ; 2040.16,-1280.5 5533.85,-1280.5 4075.46,-1280.5 ; 2280.32,-1280.5 -316.68,-1280.5 -316.68,-670.5 5533.85,-670.5 ; 2293.47,-873.83 2293.47,-670.5 ; 3324.25,-1280.5 3324.25,-670.5 ; 5532.85,-1280.5 5532.85,-670.5 ; 5533.35,-1280.5 5533.35,-670.5
  text "COMPONENTS MARKED 'DNP' SHOULD NOT BE POPULATED." at 5699.86,-464.5 h60
  text ".VariantName" at 4360.59,-580.5 h60
  text "ASSEMBLY VARIANT:" at 5360.22,-580.5 h60
  text ".VersionControl_RevNumber" at 1031,-802.67 h60
  text "SVN REV:" at 1517.32,-802.67 h60
  text ".PCB_Rev" at 1922.08,-802.67 h60
  text "REV:" at 2162.4,-802.67 h60
  text ".PRJ_Number" at 2762.81,-802.67 h60
  text "BOARD #:" at 3229.57,-802.67 h60
  text "PCB VIEWED FROM BOTTOM SIDE" at 5489.53,-802.67 h60
  text ".TID" at 2782.49,-1006 h60
  text "TID #:" at 3229.57,-1006 h60
  text "TEXAS INSTRUMENTS" at 840.94,-1211.34 h60
  text ".Print_Time" at 2022.77,-1211.34 h60
  text ".Print_Date" at 2641.53,-1211.34 h60
  text "GENERATED    :" at 3424.42,-1211.34 h60
  text ".plot_File_Name" at 4821.83,-1211.34 h60
  text "PLOT NAME =" at 5489.53,-1211.34 h60
M9 Title Sheet:
  drawing of 55 lines, arcs and shapes, not listed
  text "1" at 656.34,5185 h70
  text "2" at 3014.35,5185 h70
  text "3" at 5391,5185 h70
  text "4" at 7766.35,5185 h70
  text "A" at -441,4295 h70
  text "A" at 8854,4295 h70
  text "B" at -441,2419 h70
  text "B" at 8854,2419 h70
  text "C" at -441,543 h70
  text "C" at 8854,543 h70
  text "PROJECT TITLE:" at 5819,-569 h45
  text ".PRJ_Title" at 5869,-702.33 h70
  text "DESIGNED FOR:" at 5819,-870 h45
  text ".PRJ_Customer" at 5869,-1010 h70
  text "FILE NAME:" at 5819,-1170 h45
  text ".PCB_File_Name_No_Path" at 5869,-1290 h70
  text "D" at -441,-1329 h70
  text "D" at 8854,-1329 h70
  text "Texas Instruments (TI) and/or its licensors do not warrant the accuracy or completeness of this specification" at 959.5,-1451.84 h45
  text "ENGINEER:" at 5819,-1460 h45
  text "LAYOUT BY:" at 7324,-1460 h45
  text "or any information contained therein. TI and/or its licensors do not warrant that this design will meet" at 914.51,-1564.5 h45
  text ".PRJ_Engineer" at 5869,-1614.99 h70
  text ".PCB_Layout" at 7374.5,-1614.99 h70
  text "the specifications, will be suitable for your application or fit for any particular purpose, or will operate in" at 914.51,-1677.17 h45
  text "ALTIUM DESIGNER VERSION:" at 7324,-1770 h45
  text "an implementation. TI and/or its licensors do not warrant that the design is production worthy. You should" at 914.51,-1789.83 h45
  text "completely validate and test your design implementation to confirm the system functionality for your application." at 959.5,-1902.5 h40
  text ".print_Scale" at 5869,-1903.33 h70
  text ".Application_BuildNumber" at 7374.5,-1903.33 h70
  text "1" at 656.34,-2115 h70
  text "2" at 3014.35,-2115 h70
  text "3" at 5391,-2115 h70
  text "4" at 7766.35,-2115 h70
M10 Fab Notes:
  drawing of 189 lines, arcs and shapes, not listed
  text "DESIGN INFORMATION" at 6855.02,5015.17 h60
  text "MIN. TRACK WIDTH:" at 6210.46,4883.05 h60
  text "10" at 7306.7,4883.05 h60
  text "MIL" at 7461.46,4883.05 h60
  text "7.874" at 7135.83,4763.78 h60
  text "MIN. CLEARANCE:" at 6210.46,4758.92 h60
  text "MIL" at 7461.46,4758.92 h60
  text "MIN. VIA PAD SIZE:" at 6210.46,4634.8 h60
  text "24" at 7276.71,4634.8 h60
  text "MIL" at 7461.46,4634.8 h60
  text "0.05mm (2MIL)" at 6905.46,4504.9 h60
  text "MINIMUM ANNULAR RING" at 5881.23,4496.67 h60
  text "EXTERNAL" at 7613.46,4496.67 h60
  text "PER" at 6081.23,4386.55 h60
  text "IPC-D-275 CLASS 2 LEVEL C" at 6301.23,4386.54 h60
  text "MIL, HOLES" at 7789.46,4286.07 h60
  text "+/-" at 7397,4277.48 h60
  text "+/-" at 8251,4277.48 h60
  text "REGISTRATION TOLERANCES:" at 5881.23,4276.42 h60
  text "METAL" at 7081,4276.42 h60
  text "5" at 7657.2,4276.42 h60
  text "3" at 8490.2,4276.42 h60
  text "MIL" at 8606.46,4276.42 h60
  text "HOLE SIZE TOLERANCE (UNLESS OTHERWISE SPECIFIED):" at 5881.23,4178.1 h60
  text "+/-" at 8251,4175.23 h60
  text "3" at 8490.2,4174.17 h60
  text "MIL" at 8606.46,4174.17 h60
  text "MATERIAL:" at 5806.46,4036.52 h60
  text "FR-4 High Tg" at 6792.9,3908 h60
  text "X" at 6648.46,3900.01 h60
  text "FR-408" at 6227.46,3895.49 h60
  text "OTHER" at 7715.46,3895.49 h60
  text "62 MIL (1.6mm) +/-10%" at 6547.56,3752.46 h60
  text "X" at 6427.46,3750.01 h60
  text "THICKNESS:" at 5881.23,3744.24 h60
  text "OTHER" at 7832.46,3744.24 h60
  text "TOLERANCE:" at 5881.23,3605.92 h60
  text "X" at 6729.46,3605.92 h60
  text "ANSI IPC-6012 TYPE 3 CLASS 2" at 6907.48,3605.92 h60
  text "OTHER +/-" at 6907.46,3461.73 h60
  text "BOW & TWIST:" at 5881.23,3316.54 h60
  text "X" at 6729.46,3316.54 h60
  text "ANSI IPC-6012 TYPE 3 CLASS 2" at 6907.48,3316.54 h60
  text "OTHER +/-" at 6907.46,3169.85 h60
  text "DRILLING:" at 5806.46,3039.23 h60
  text "NC_DRILL FILES" at 7567.46,2934.04 h60
  text "REFERENCE:" at 5881.23,2930.1 h60
  text "X" at 6538.46,2930.01 h60
  text "AS SHOWN" at 6716.46,2930.1 h60
  text "X" at 7439.46,2930.1 h60
  text "OTHER" at 7865.46,2787.85 h60
  text "PTH COPPER THICKNESS:" at 5880.91,2784.32 h60
  text "X" at 7020.14,2784.32 h60
  text "20-30 um" at 7148.14,2784.32 h60
  text "BOARD FINISH:" at 5806.46,2636.73 h60
  text "SILKSCREEN:" at 5961.68,2526.6 h60
  text "X" at 6919.46,2526.6 h60
  text "TOP" at 7036.46,2526.6 h60
  text "X" at 7429.46,2526.6 h60
  text "BOTTOM" at 7547.46,2526.6 h60
  text "SILKSCREEN COLOR:" at 5961.68,2371.41 h60
  text "X" at 6918.46,2371.41 h60
  text "WHITE" at 7036.46,2371.41 h60
  text "OTHER" at 7547.46,2371.41 h60
  text "X" at 7049.46,2227.96 h60
  text "GREEN" at 7167.46,2227.96 h60
  text "OTHER" at 7785.46,2227.96 h60
  text "SOLDER RESIST COLOR:" at 5961.68,2221.1 h60
  text "X" at 7049.46,2073.71 h60
  text "MATTE" at 7167.46,2073.71 h60
  text "SEMI-GLOSS" at 7785,2073.07 h60
  text "IMMERSION GOLD (ENIG)" at 6867.46,1900.94 h60
  text "ENEPIG" at 8205,1893.72 h60
  text "SURFACE FINISH:" at 5806.46,1892.72 h60
  text "X" at 6689.46,1892.72 h60
  text "IMM. TIN/SILVER OR EQUIV" at 6136,1755.4 h60
  text "OTHER" at 7567.46,1751.47 h60
  text "ARRAY/PANEL:" at 5806.46,1596.09 h60
  text "CUT AND TRIM PER M1 BOARD OUTLINE" at 6867.46,1587.87 h60
  text "N.C. ROUTE" at 6867.46,1451.9 h60
  text "X" at 7555.46,1451.9 h60
  text "V. SCORE" at 7733.46,1451.9 h60
  text "CERTIFICATION:" at 5806.46,1322.77 h60
  text "MATERIALS AND WORKMANSHIP FOR ALL PCBS" at 6531.46,1322.77 h60
  text "TO MEET OR EXCEED THE REQUIREMENTS OF:" at 6531.46,1228.71 h60
  text "X" at 6168.97,1100.08 h60
  text "ANSI IPC-A-600F CLASS ->" at 6296.96,1100.08 h60
  text "X" at 7944.97,1100.08 h60
  text "2" at 8054.96,1100.08 h60
  text "1" at 7739.96,1098.58 h60
  text "3" at 8408.96,1098.58 h60
  text "X" at 6980.97,952.39 h60
  text "RoHS" at 7108.96,952.39 h60
  text "OTHER" at 7753.36,952.39 h60
  text "PER ORDER" at 8150.42,952.39 h60
  text "ALL BOARDS MUST MEET OR EXCEED UL94-V0 REQUIREMENTS." at 5834,798.57 h60
  text "PCB MUST BEAR THE UL94V-0 UL REGISTERED MATERIAL ID NUMBER" at 5834,682.5 h60
  text "ADDITIONAL REQUIREMENTS:" at 5806.46,513.08 h60
  text "MICROSECTION:" at 5881.23,405.95 h60
  text "YES" at 6786.96,405.95 h60
  text "REQUIRED" at 7648.46,261.62 h60
  text "BARE BOARD ELEC. TEST:" at 5881.23,258.76 h60
  text "NONE" at 7186.96,258.76 h60
  text "X" at 7530.46,258.76 h60
  text "PER ORDER" at 8240.46,258.76 h60
  text "XX MIL VIAS REQUIRE NON-CONDUCTIVE FILL AND PLANARIZE" at 6049.38,53.82 h59
  text "XX MIL VIAS REQUIRE CONDUCTIVE FILL AND PLANARIZE" at 6057.38,-50.16 h60
  text "OUTER XX MIL TRACES REQUIRE 50 OHM SINGLE-ENDED IMPEDANCE" at 6056.39,-213.54 h58
  text "LAYER 2 & 3 (INNER LAYERS) XX MIL WIDE, XX MIL SPACE / TRACES REQUIRE 100 OHM DIFFERENTIAL IMPEDANCE" at 6048.39,-449.26 h60
  text ".Layer_Name" at 493.76,-1004.99 h60
M11 Gerber Information:
  lines w10: -316.18,-1076.67 5533.85,-1076.67 ; -316.18,-873.33 5533.85,-873.33 ; -316.18,-670 -316.18,-1280 3688.82,-1280 ; 1259.82,-1280 -315.68,-1280 -315.68,-670 5533.85,-670 5533.85,-1280 3212.44,-1280 ; 1967.71,-1280 1967.71,-670 ; 2998.49,-873.33 2998.49,-670 ; 3720.38,-873.33 3720.38,-670 ; 4224.27,-1286.5 4224.27,-1083.67
  text "ALL ARTWORK VIEWED FROM TOP SIDE" at -272.37,-802.17 h60
  text "BOARD #:" at 2011.22,-802.17 h60
  text ".PRJ_Number" at 2470.1,-802.17 h60
  text "REV:" at 3157.12,-802.17 h60
  text ".PCB_Rev" at 3389.57,-802.17 h60
  text "SVN REV:" at 3790.4,-802.17 h60
  text ".VersionControl_RevNumber" at 4284.59,-802.17 h60
  text "LAYER NAME =" at -272.37,-1004.99 h60
  text "TID #:" at 2011.22,-1005.5 h60
  text ".TID" at 2470.1,-1005.5 h60
  text "PLOT NAME =" at -272.37,-1210.84 h60
  text ".plot_File_Name" at 493.76,-1210.84 h60
  text "GENERATED    :" at 2013.22,-1210.84 h60
  text ".Print_Date" at 2737.05,-1210.84 h60
  text ".Print_Time" at 3328.25,-1210.84 h60
  text "TEXAS INSTRUMENTS" at 4395.9,-1210.84 h60
M12 Stackup:
  drawing of 191 lines, arcs and shapes, not listed
  text "Layer" at 1093.5,4843 h60
  text "Name" at 1503.41,4843 h60
  text "Material" at 2433.16,4843 h60
  text "Thickness" at 3292.92,4843 h60
  text "Constant" at 3942.76,4843 h60
  text "Board Layer Stack" at 4512.62,4843 h60
  text "Top Overlay" at 1503.41,4723 h60
  text "Top Solder" at 1503.41,4603 h60
  text "Solder Resist" at 2433.16,4603 h60
  text "0.40mil" at 3292.92,4603 h60
  text "3.5" at 3942.76,4603 h60
  text "1" at 1093.5,4483 h60
  text "Top Layer" at 1503.41,4483 h60
  text "1.40mil" at 3292.92,4483 h60
  text "Dielectric1" at 1503.41,4363 h60
  text "FR-4 High Tg" at 2433.16,4363 h60
  text "58.40mil" at 3292.92,4363 h60
  text "4.8" at 3942.76,4363 h60
  text "2" at 1093.5,4243 h60
  text "Bottom Layer" at 1503.41,4243 h60
  text "1.40mil" at 3292.92,4243 h60
  text "Bottom Solder" at 1503.41,4123 h60
  text "Solder Resist" at 2433.16,4123 h60
  text "0.40mil" at 3292.92,4123 h60
  text "3.5" at 3942.76,4123 h60
  text "Bottom Overlay" at 1503.41,4003 h60
  text ".Layer_Name" at 493.76,-1004.99 h60
M13 Component Bodies Top:
  text ".Layer_Name" at 493.76,-1004.99 h60
M14 Component Bodies Bottom:
  text ".Layer_Name" at 493.76,-1004.99 h60
M15 Courtyards Top:
  text ".Layer_Name" at 493.76,-1004.99 h60
M16 Courtyards Bottom:
  text ".Layer_Name" at 493.76,-1004.99 h60
Drill Drawing:
  circle w10: c2531.72,3576.28 r27.63
  lines w10: 2504.09,3424.34 2559.34,3424.34 2559.34,3479.59 2504.09,3479.59 2504.09,3424.34
  lines w12: 2454,3387.04 5685.49,3387.04 ; 2454,3635.68 5685.49,3635.68 ; 2791.86,3262.72 2791.86,3760 ; 3123.86,3262.72 3123.86,3760 ; 3760.43,3262.72 3760.43,3760 ; 4019.57,3262.72 4019.57,3760 ; 4394.72,3262.72 4394.72,3760 ; 5119.05,3262.72 5119.05,3760 ; 2454,3262.72 5685.49,3262.72 5685.49,3760 2454,3760 2454,3262.72
  text "Symbol" at 2528.59,3672.98 h72
  text "Quantity" at 2829.16,3672.98 h72
  text "Finished Hole Size" at 3161.16,3672.98 h72
  text "Plated" at 3797.72,3672.98 h72
  text "Hole Type" at 4056.86,3672.98 h72
  text "Drill Layer Pair" at 4432.02,3672.98 h72
  text "Hole Tolerance" at 5156.35,3672.98 h72
  text "44" at 2829.16,3548.66 h60
  text "10.00mil (0.254mm)" at 3161.16,3548.66 h60
  text "PTH" at 3797.72,3548.66 h60
  text "Round" at 4056.86,3548.66 h60
  text "Top Layer - Bottom Layer" at 4432.02,3548.66 h60
  text "10" at 2829.16,3424.34 h60
  text "43.31mil (1.100mm)" at 3161.16,3424.34 h60
  text "PTH" at 3797.72,3424.34 h60
  text "Round" at 4056.86,3424.34 h60
  text "Top Layer - Bottom Layer" at 4432.02,3424.34 h60
  text "+/-1.97mil" at 5156.35,3424.34 h60
  text "54 Total" at 2829.16,3300.02 h60
  text ".Layer_Name" at 493.76,-1004.99 h60
M17 Embedded Cavity:
  text ".Layer_Name" at 493.76,-1004.99 h60
M18 Embedded Assembly:
  text ".Layer_Name" at 493.76,-1004.99 h60
M19 Embedded Keepout:
  text ".Layer_Name" at 497.7,-1008.93 h60

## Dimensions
0,0 to 0,1062.99 on M2 Board Dimensions
0,0 to 2000,0 on M2 Board Dimensions
-4.5,-546.5 to 995.5,-546.5 on M2 Board Dimensions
